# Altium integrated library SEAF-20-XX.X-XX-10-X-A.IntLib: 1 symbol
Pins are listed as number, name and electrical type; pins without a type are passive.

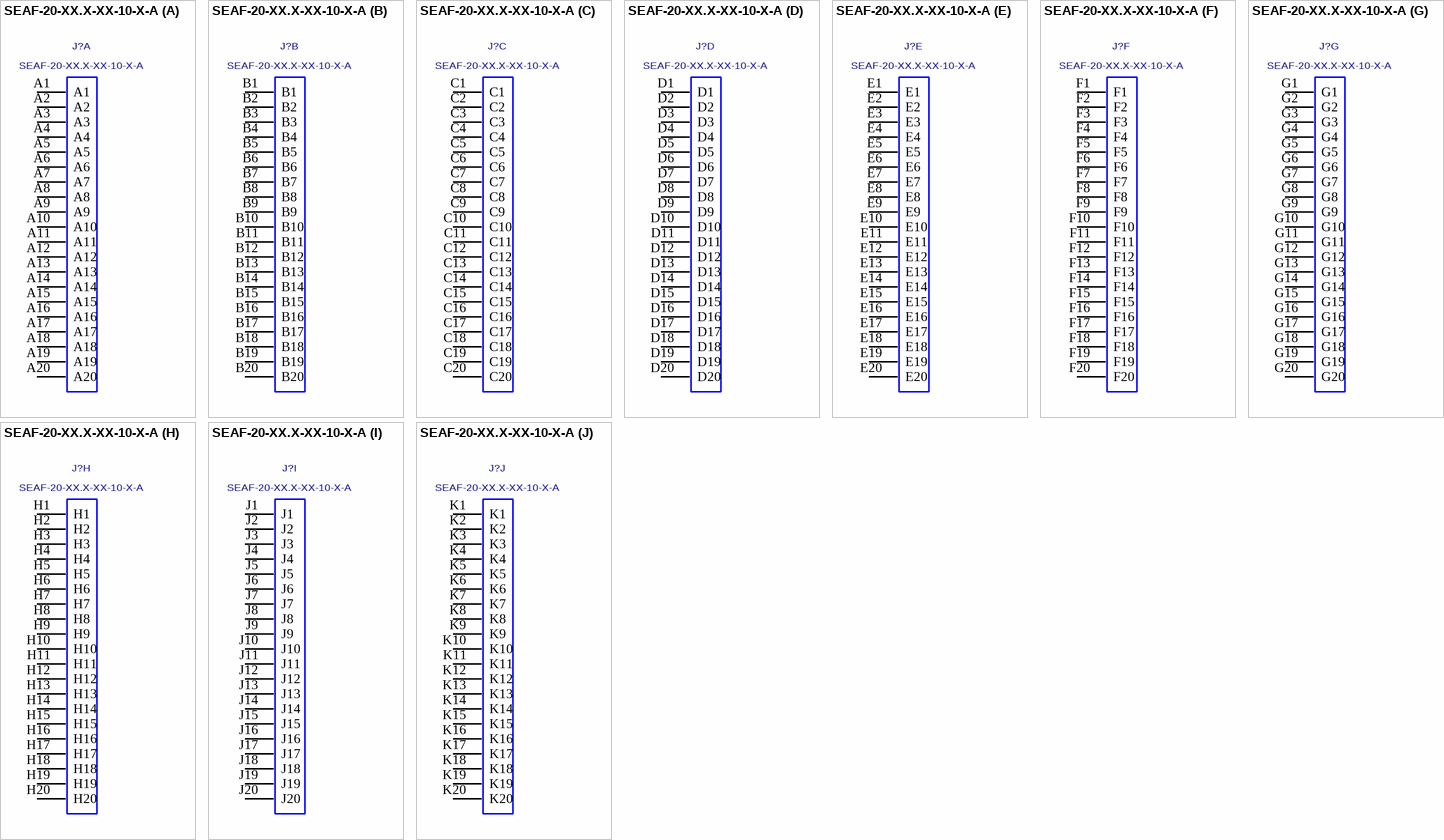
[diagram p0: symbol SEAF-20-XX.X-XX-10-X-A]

## SEAF-20-XX.X-XX-10-X-A
designator J?
Socket Array Assembly, Surface Mount, 0.050" Pitch, 200 Pins; MANUFACTURER: SAMTEC
footprint SEAF-20-XX.X-XX-10-X-A
part A pins: A1, A2, A3, A4, A5, A6, A7, A8, A9, A10, A11, A12, A13, A14, A15, A16, A17, A18, A19, A20
part B pins: B1, B2, B3, B4, B5, B6, B7, B8, B9, B10, B11, B12, B13, B14, B15, B16, B17, B18, B19, B20
part C pins: C1, C2, C3, C4, C5, C6, C7, C8, C9, C10, C11, C12, C13, C14, C15, C16, C17, C18, C19, C20
part D pins: D1, D2, D3, D4, D5, D6, D7, D8, D9, D10, D11, D12, D13, D14, D15, D16, D17, D18, D19, D20
part E pins: E1, E2, E3, E4, E5, E6, E7, E8, E9, E10, E11, E12, E13, E14, E15, E16, E17, E18, E19, E20
part F pins: F1, F2, F3, F4, F5, F6, F7, F8, F9, F10, F11, F12, F13, F14, F15, F16, F17, F18, F19, F20
part G pins: G1, G2, G3, G4, G5, G6, G7, G8, G9, G10, G11, G12, G13, G14, G15, G16, G17, G18, G19, G20
part H pins: H1, H2, H3, H4, H5, H6, H7, H8, H9, H10, H11, H12, H13, H14, H15, H16, H17, H18, H19, H20
part I pins: J1, J2, J3, J4, J5, J6, J7, J8, J9, J10, J11, J12, J13, J14, J15, J16, J17, J18, J19, J20
part J pins: K1, K2, K3, K4, K5, K6, K7, K8, K9, K10, K11, K12, K13, K14, K15, K16, K17, K18, K19, K20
